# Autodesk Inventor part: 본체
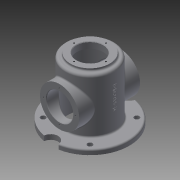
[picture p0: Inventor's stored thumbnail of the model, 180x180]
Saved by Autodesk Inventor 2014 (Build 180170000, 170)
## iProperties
Created: 2018-04
Part Number: 본체
Material: 일반
Document SubType Name: Modeling
Designer: net
Density: 1 g/cm^3
Appearance: 기본값
Author: net
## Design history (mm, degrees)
sketch "스케치1"
  geometry: L1 (0, 66.5)-(0, -66.5); L2 (27, 66.5)-(40, 66.5); L3 (40, 66.5)-(40, 61.5); L4 (27, 66.5)-(27, 53.5); L5 (27, 53.5)-(45, 53.5); L6 (45, 53.5)-(45, -66.5); L7 (45, -66.5)-(50, -66.5); L8 (50, 61.5)-(50, -66.5); L9 (40, 61.5)-(50, 61.5); 2 further points
  constraints: 18 end point, 6 perpendicular, 2 horizontal alignment, 1 coincident, 1 midpoint, 1 vertical
  dimensions: "d0" = 133 distance of L1.start L1.end; "d1" = 54 diameter of L4 L1; "d2" = 80 diameter of L3 L1; "d3" = 90 diameter of L6 L1; "d5" = 100 diameter of L8 L1; "d8" = 120 distance from line of L1.end L5; "d9" = 128 distance of L8.start L7.end
revolve "회전1" sketch "스케치1" stored, may be unused: angle "d10" = 90 deg
node "작업 평면1"
sketch "스케치2"
  geometry: L1 (-50, -66.5)-(50, -66.5) reference; C1 r 40 at (0, 1.5); 1 further point
  constraints: 1 centre point, 1 vertical alignment
  dimensions: "d12" = 80 diameter of C1; "d13" = 68 distance from line of C1.centre L1
extrude "돌출1" join sketch "스케치2" stored distance "d14" = 10; taper "d15" = 0 deg
hole "구멍1" diameter "d18" = 54; stored, may be unused: countersink angle "d22" = 90 deg, drill point angle "d24" = 118 deg; dims "d16" = 10, "d17" = 10, "d19" = 6, "d20" = 4, "d21" = 2, "d23" = 8
node "작업 평면2"
sketch "스케치3"
  geometry: C1 r 15 at (0, -80); C2 r 15 at (0, 80); A1 r 80 centre (0, 0) between (0, 80) and (0, -80); 1 further point
  constraints: 3 centre point, 2 point on circle, 2 vertical alignment, 1 coincident, 1 equal radius
  dimensions: "d26" = 160 diameter of A1; "d57" = 30 diameter of C2
extrude "돌출2" join sketch "스케치3" distance "d31" = 10; taper "d32" = 0 deg
sketch "스케치4"
  geometry: C1 r 27 at (0, 0) reference; 2 further points
  constraints: 1 vertical alignment
  dimensions: "d35" = 32.5 distance of C1.centre point (0, 32.5)
hole "구멍2" sketch "스케치4" at (0, 32.5) diameter "d36" = 3.242; stored, may be unused: countersink angle "d40" = 90 deg, drill point angle "d42" = 118 deg; dims "d37" = 8, "d38" = 4, "d39" = 2, "d41" = 10
sketch "스케치5"
  geometry: C1 r 40 at (0, 0) reference; 1 further point
  constraints: 1 vertical alignment
  dimensions: "d46" = 32.5 distance of point (0, 32.5) C1.centre
hole "구멍3" sketch "스케치5" at (0, 32.5) diameter "d47" = 3.242; stored, may be unused: countersink angle "d51" = 90 deg, drill point angle "d53" = 118 deg; dims "d48" = 8, "d49" = 4, "d50" = 2, "d52" = 10
extrude "돌출4" cut sketch "스케치3" distance "d58" = 10; taper "d59" = 0 deg
sketch "스케치6" dims "d64" = 135
  geometry: L1 (0, 0)-(80, 0); L2 (0, 0)-(47.73, 47.73); C1 r 50 at (0, 0) reference; C2 r 5 at (47.73, 47.73); A1 r 80 centre (0, 0) between (14.934, -78.594) and (14.934, 78.594) reference
  constraints: 4 end point, 1 centre point, 1 coincident, 1 point on circle, 3 other
  dimensions: "d60" = 10 diameter of C2; "d66" = 45 deg angle of L1 L2
extrude "돌출5" cut sketch "스케치6" distance "d67" = 10; taper "d68" = 0 deg
fillet "모깎기1" dims "d69" = 5
hole "구멍4" diameter "d72" = 90; stored, may be unused: countersink angle "d76" = 90 deg, drill point angle "d78" = 118 deg; dims "d70" = 10, "d71" = 10, "d73" = 8, "d74" = 4, "d75" = 2, "d77" = 20
fillet "모깎기2" dims "d79" = 3
fillet "모깎기3" dims "d80" = 3
chamfer "모따기1" distance "d81" = 1; stored, may be unused: second distance "d82" = 2, angle "d83" = 45 deg
node "작업 평면3"
sketch "스케치7"
  geometry: L1 (-78.594, -56)-(78.594, -56) reference; 2 further points
  constraints: 1 vertical alignment, 1 other
  dimensions: "d85" = 70 distance from line of point (0, 14) L1
feature "엠보싱1" sketch "스케치7" dims "d20" = 4, "d86" = 0.5, "d87" = 0
fillet "모깎기5" dims "d88" = 3
fillet "모깎기6" dims "d89" = 3
chamfer "모따기2" distance "d90" = 1; stored, may be unused: second distance "d91" = 2, angle "d92" = 45 deg
node "솔리드1"
mirror "대칭1"
pattern_circular "원형 패턴1" dims angle "d44" = 360 deg
mirror "대칭2"
pattern_circular "원형 패턴2" dims angle "d55" = 360 deg
mirror "대칭3"
mirror "대칭4"
other parameters: "d11" = -62, "d25" = -8
